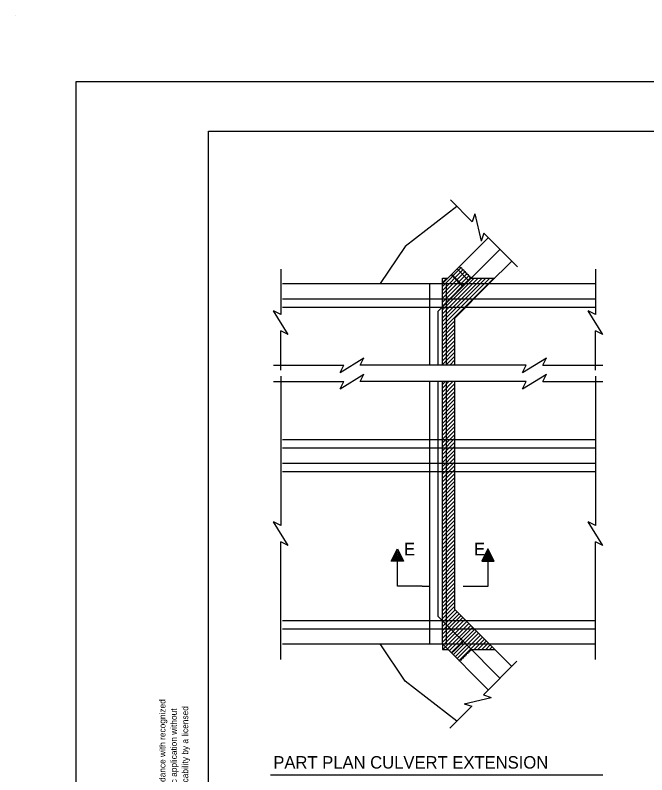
# Model space of a CAD drawing. Extents: x -0.08 to 2.83, y -0.03 to 1.92.
# Drawn here: x -0.077 to 0.718, y 0.961 to 1.917 of the extents above; entities that cross this region are included whole.
import ezdxf

# ---------------------------------------------------------------- set-up
doc = ezdxf.new("R2010")
doc.units = 0
for name, color, linetype in [('21', 7, 'Continuous'), ('50', 7, 'Continuous'), ('55', 7, 'Continuous'), ('57', 7, 'Continuous'), ('63', 7, 'Continuous')]:
    doc.layers.add(name, color=color, linetype=linetype)

msp = doc.modelspace()

# ---------------------------------------------------------------- linework, layer by layer
at = {"layer": '21'}
msp.add_line((-0.07667, 1.91667), (-0.07667, 1.91667), dxfattribs=at)
at = {"layer": '50'}
for p, q in [((0.47931, 1.67622), (0.41428, 1.62579)), ((0.46093, 1.57914), (0.51866, 1.63687)), ((0.41428, 1.62579), (0.38281, 1.57914)), ((0.49039, 1.57914), (0.5334, 1.62214)), ((0.51986, 1.57914), (0.54813, 1.60741)), ((0.49408, 1.58282), (0.47935, 1.59756)), ((0.47608, 1.58609), (0.47198, 1.59019)), ((0.48702, 1.57577), (0.47229, 1.5905)), ((0.47731, 1.58609), (0.47259, 1.5908)), ((0.48671, 1.57546), (0.47608, 1.58609)), ((0.48732, 1.57607), (0.47731, 1.58609)), ((0.25975, 1.57914), (0.46614, 1.57914)), ((0.44531, 1.47671), (0.44531, 1.57914)), ((0.46093, 1.47671), (0.46093, 1.57914)), ((0.46614, 1.47671), (0.46614, 1.57914)), ((0.46614, 1.57914), (0.65364, 1.57914)), ((0.4713, 1.56004), (0.49039, 1.57914)), ((0.47656, 1.53584), (0.51986, 1.57914)), ((0.25975, 1.56004), (0.65364, 1.56004)), ((0.45572, 1.54447), (0.4713, 1.56004)), ((0.46614, 1.56004), (0.4713, 1.56004)), ((0.25975, 1.54963), (0.65364, 1.54963)), ((0.45572, 1.47671), (0.45572, 1.54447)), ((0.47656, 1.47671), (0.47656, 1.53584)), ((0.44531, 1.12602), (0.44531, 1.45588)), ((0.45572, 1.16069), (0.45572, 1.45588)), ((0.46093, 1.12602), (0.46093, 1.45588)), ((0.46614, 1.12602), (0.46614, 1.45588)), ((0.47656, 1.16932), (0.47656, 1.45588)), ((0.25975, 1.38296), (0.65364, 1.38296)), ((0.25975, 1.37254), (0.65364, 1.37254)), ((0.25975, 1.35345), (0.65364, 1.35345)), ((0.25975, 1.34303), (0.65364, 1.34303)), ((0.47656, 1.16932), (0.51986, 1.12602)), ((0.45572, 1.16069), (0.4713, 1.14511)), ((0.25975, 1.15553), (0.65364, 1.15553)), ((0.25975, 1.14511), (0.65364, 1.14511)), ((0.46614, 1.14511), (0.4713, 1.14511)), ((0.4713, 1.14511), (0.49039, 1.12602)), ((0.48702, 1.12939), (0.47229, 1.11466)), ((0.48671, 1.1297), (0.47608, 1.11907)), ((0.48732, 1.12909), (0.47731, 1.11907)), ((0.25975, 1.12602), (0.46614, 1.12602)), ((0.41428, 1.07937), (0.38281, 1.12602)), ((0.46093, 1.12602), (0.51866, 1.06828)), ((0.46614, 1.12602), (0.65364, 1.12602)), ((0.47608, 1.11907), (0.47198, 1.11497)), ((0.47731, 1.11907), (0.47259, 1.11435)), ((0.49408, 1.12233), (0.47935, 1.1076)), ((0.49039, 1.12602), (0.5334, 1.08301)), ((0.51986, 1.12602), (0.54813, 1.09775)), ((0.47931, 1.02893), (0.41428, 1.07937))]:
    msp.add_line(p, q, dxfattribs=at)
for points in [[(0.47514, 1.58822), (0.473, 1.59036), (0.47242, 1.58979), (0.47457, 1.58764)], [(0.47729, 1.58607), (0.47514, 1.58822), (0.47457, 1.58764), (0.47671, 1.5855)], [(0.4848, 1.57856), (0.48266, 1.5807), (0.48208, 1.58013), (0.48423, 1.57798)], [(0.48695, 1.57641), (0.4848, 1.57856), (0.48423, 1.57798), (0.48637, 1.57584)], [(0.4848, 1.1266), (0.48266, 1.12446), (0.48208, 1.12503), (0.48423, 1.12718)], [(0.48695, 1.12875), (0.4848, 1.1266), (0.48423, 1.12718), (0.48637, 1.12932)], [(0.47729, 1.11909), (0.47514, 1.11694), (0.47457, 1.11751), (0.47671, 1.11966)], [(0.47514, 1.11694), (0.473, 1.11479), (0.47242, 1.11537), (0.47457, 1.11751)]]:
    msp.add_lwpolyline(points, close=True, dxfattribs=at)
at = {"layer": '55'}
for p, q in [((0.47101, 1.68452), (0.49851, 1.65703)), ((0.50177, 1.66684), (0.49851, 1.65703)), ((0.50177, 1.66684), (0.50979, 1.63267)), ((0.51306, 1.64248), (0.50979, 1.63267)), ((0.55531, 1.60023), (0.51306, 1.64248)), ((0.25781, 1.59719), (0.25781, 1.54018)), ((0.46093, 1.5755), (0.48463, 1.5992)), ((0.46093, 1.57059), (0.48703, 1.59668)), ((0.65364, 1.59719), (0.65364, 1.54018)), ((0.46093, 1.56568), (0.48965, 1.59439)), ((0.46093, 1.56077), (0.4915, 1.59133)), ((0.46093, 1.55586), (0.49417, 1.58909)), ((0.46093, 1.55095), (0.4969, 1.58692)), ((0.46093, 1.58532), (0.4617, 1.58609)), ((0.46093, 1.58041), (0.46661, 1.58609)), ((0.46093, 1.54603), (0.50098, 1.58609)), ((0.46093, 1.54112), (0.50589, 1.58609)), ((0.46093, 1.53621), (0.5108, 1.58609)), ((0.46093, 1.5313), (0.51571, 1.58609)), ((0.46093, 1.52639), (0.52062, 1.58609)), ((0.46093, 1.52148), (0.52553, 1.58609)), ((0.46093, 1.57914), (0.46093, 1.58609)), ((0.46093, 1.58609), (0.46788, 1.58609)), ((0.49734, 1.58609), (0.5268, 1.58609)), ((0.25781, 1.54018), (0.24855, 1.5448)), ((0.26705, 1.51496), (0.24855, 1.5448)), ((0.65364, 1.54018), (0.64439, 1.5448)), ((0.66289, 1.51496), (0.64439, 1.5448)), ((0.46093, 1.51657), (0.47656, 1.5322)), ((0.25781, 1.47047), (0.25781, 1.51959)), ((0.26705, 1.51496), (0.25781, 1.51959)), ((0.46093, 1.51166), (0.47656, 1.52729)), ((0.46093, 1.50675), (0.47656, 1.52238)), ((0.65364, 1.47047), (0.65364, 1.51959)), ((0.66289, 1.51496), (0.65364, 1.51959)), ((0.46093, 1.50184), (0.47656, 1.51747)), ((0.46093, 1.49693), (0.47656, 1.51256)), ((0.46093, 1.49202), (0.47656, 1.50764)), ((0.46093, 1.48711), (0.47656, 1.50273)), ((0.46093, 1.4822), (0.47656, 1.49782)), ((0.46093, 1.47729), (0.47656, 1.49291)), ((0.3321, 1.46746), (0.36193, 1.48596)), ((0.35731, 1.47671), (0.36193, 1.48596)), ((0.46526, 1.47671), (0.47656, 1.488)), ((0.47017, 1.47671), (0.47656, 1.48309)), ((0.56194, 1.46746), (0.59177, 1.48596)), ((0.58715, 1.47671), (0.59177, 1.48596)), ((0.24855, 1.47671), (0.33672, 1.47671)), ((0.3321, 1.46746), (0.33672, 1.47671)), ((0.56656, 1.47671), (0.35731, 1.47671)), ((0.47508, 1.47671), (0.47656, 1.47818)), ((0.56194, 1.46746), (0.56656, 1.47671)), ((0.58715, 1.47671), (0.66289, 1.47671)), ((0.25781, 1.46276), (0.25781, 1.27503)), ((0.3321, 1.44663), (0.36193, 1.46513)), ((0.35731, 1.45588), (0.36193, 1.46513)), ((0.56194, 1.44663), (0.59177, 1.46513)), ((0.58715, 1.45588), (0.59177, 1.46513)), ((0.65364, 1.46276), (0.65364, 1.27503)), ((0.24855, 1.45588), (0.33672, 1.45588)), ((0.3321, 1.44663), (0.33672, 1.45588)), ((0.56656, 1.45588), (0.35731, 1.45588)), ((0.46093, 1.45247), (0.46434, 1.45588)), ((0.46093, 1.44756), (0.46925, 1.45588)), ((0.46093, 1.44265), (0.47416, 1.45588)), ((0.46093, 1.43774), (0.47656, 1.45336)), ((0.56194, 1.44663), (0.56656, 1.45588)), ((0.58715, 1.45588), (0.66289, 1.45588)), ((0.46093, 1.43283), (0.47656, 1.44845)), ((0.46093, 1.42792), (0.47656, 1.44354)), ((0.46093, 1.42301), (0.47656, 1.43863)), ((0.46093, 1.4181), (0.47656, 1.43372)), ((0.46093, 1.41319), (0.47656, 1.42881)), ((0.46093, 1.40827), (0.47656, 1.4239)), ((0.46093, 1.40336), (0.47656, 1.41899)), ((0.46093, 1.39845), (0.47656, 1.41408)), ((0.46093, 1.39354), (0.47656, 1.40917)), ((0.46093, 1.38863), (0.47656, 1.40426)), ((0.46093, 1.38372), (0.47656, 1.39935)), ((0.46093, 1.37881), (0.47656, 1.39444)), ((0.46093, 1.3739), (0.47656, 1.38953)), ((0.46093, 1.36899), (0.47656, 1.38462)), ((0.46093, 1.36408), (0.47656, 1.37971)), ((0.46093, 1.35917), (0.47656, 1.3748)), ((0.46093, 1.35426), (0.47656, 1.36988)), ((0.46093, 1.34935), (0.47656, 1.36497)), ((0.46093, 1.34444), (0.47656, 1.36006)), ((0.46093, 1.33953), (0.47656, 1.35515)), ((0.46093, 1.33462), (0.47656, 1.35024)), ((0.46093, 1.32971), (0.47656, 1.34533)), ((0.46093, 1.3248), (0.47656, 1.34042)), ((0.46093, 1.31989), (0.47656, 1.33551)), ((0.46093, 1.31498), (0.47656, 1.3306)), ((0.46093, 1.31007), (0.47656, 1.32569)), ((0.46093, 1.30516), (0.47656, 1.32078)), ((0.46093, 1.30024), (0.47656, 1.31587)), ((0.46093, 1.29533), (0.47656, 1.31096)), ((0.46093, 1.29042), (0.47656, 1.30605)), ((0.46093, 1.28551), (0.47656, 1.30114)), ((0.46093, 1.2806), (0.47656, 1.29623)), ((0.46093, 1.27569), (0.47656, 1.29132)), ((0.46093, 1.27078), (0.47656, 1.28641)), ((0.46093, 1.26587), (0.47656, 1.2815)), ((0.25781, 1.27503), (0.24855, 1.27965)), ((0.26705, 1.24982), (0.24855, 1.27965)), ((0.46093, 1.26096), (0.47656, 1.27659)), ((0.46093, 1.25605), (0.47656, 1.27168)), ((0.65364, 1.27503), (0.64439, 1.27965)), ((0.66289, 1.24982), (0.64439, 1.27965)), ((0.46093, 1.25114), (0.47656, 1.26677)), ((0.46093, 1.24623), (0.47656, 1.26185)), ((0.25781, 1.10659), (0.25781, 1.25445)), ((0.26705, 1.24982), (0.25781, 1.25445)), ((0.46093, 1.24132), (0.47656, 1.25694)), ((0.46093, 1.23641), (0.47656, 1.25203)), ((0.65364, 1.10659), (0.65364, 1.25445)), ((0.66289, 1.24982), (0.65364, 1.25445)), ((0.46093, 1.2315), (0.47656, 1.24712)), ((0.46093, 1.22659), (0.47656, 1.24221)), ((0.46093, 1.22168), (0.47656, 1.2373)), ((0.46093, 1.21677), (0.47656, 1.23239)), ((0.46093, 1.21186), (0.47656, 1.22748)), ((0.46093, 1.20695), (0.47656, 1.22257)), ((0.46093, 1.20204), (0.47656, 1.21766)), ((0.46093, 1.19712), (0.47656, 1.21275)), ((0.46093, 1.19221), (0.47656, 1.20784)), ((0.43551, 1.19869), (0.44531, 1.19869)), ((0.46093, 1.1873), (0.47656, 1.20293)), ((0.46093, 1.18239), (0.47656, 1.19802)), ((0.46093, 1.17748), (0.47656, 1.19311)), ((0.46093, 1.17257), (0.47656, 1.1882)), ((0.46093, 1.16766), (0.47656, 1.18329)), ((0.46093, 1.16275), (0.47656, 1.17838)), ((0.46093, 1.15784), (0.47656, 1.17347)), ((0.46093, 1.15293), (0.47694, 1.16894)), ((0.46093, 1.14802), (0.47939, 1.16648)), ((0.46093, 1.14311), (0.48185, 1.16403)), ((0.46093, 1.1382), (0.4843, 1.16157)), ((0.46093, 1.13329), (0.48676, 1.15912)), ((0.46093, 1.12838), (0.48921, 1.15666)), ((0.46093, 1.12347), (0.49167, 1.1542)), ((0.46145, 1.11907), (0.49412, 1.15175)), ((0.46636, 1.11907), (0.49658, 1.14929)), ((0.46957, 1.11738), (0.49903, 1.14684)), ((0.47203, 1.11492), (0.50149, 1.14438)), ((0.47448, 1.11247), (0.50394, 1.14193)), ((0.47694, 1.11001), (0.5064, 1.13947)), ((0.47939, 1.10756), (0.50885, 1.13702)), ((0.48185, 1.1051), (0.51131, 1.13456)), ((0.50073, 1.11907), (0.51376, 1.13211)), ((0.50564, 1.11907), (0.51622, 1.12965)), ((0.51055, 1.11907), (0.51868, 1.1272)), ((0.46093, 1.12602), (0.46093, 1.11907)), ((0.46093, 1.11907), (0.46788, 1.11907)), ((0.49734, 1.11907), (0.5268, 1.11907)), ((0.51546, 1.11907), (0.52113, 1.12474)), ((0.52037, 1.11907), (0.52359, 1.12229)), ((0.52528, 1.11907), (0.52604, 1.11983)), ((0.55481, 1.10442), (0.51256, 1.06218)), ((0.51256, 1.06218), (0.52237, 1.0589)), ((0.48819, 1.05089), (0.52237, 1.0589)), ((0.48819, 1.05089), (0.498, 1.04762)), ((0.47051, 1.02013), (0.498, 1.04762))]:
    msp.add_line(p, q, dxfattribs=at)
for points in [[(0.43551, 1.19869), (0.40426, 1.19869), (0.40426, 1.22994), (0.39653, 1.22994), (0.40434, 1.24557), (0.41216, 1.22994), (0.40437, 1.22994), (0.40426, 1.23111), (0.39811, 1.23111), (0.40436, 1.24361), (0.41061, 1.23111), (0.40437, 1.23111), (0.40426, 1.23204), (0.39938, 1.23204), (0.40438, 1.24204), (0.40938, 1.23204), (0.40437, 1.23204), (0.40426, 1.23298), (0.4008, 1.23298), (0.40432, 1.24002), (0.40784, 1.23298), (0.40437, 1.23298), (0.40426, 1.23395), (0.40182, 1.23395), (0.40431, 1.23891), (0.40679, 1.23395), (0.40437, 1.23395), (0.40426, 1.23452), (0.40286, 1.23452), (0.4043, 1.23741), (0.40574, 1.23452), (0.40437, 1.23452), (0.40426, 1.23508), (0.40373, 1.23508), (0.40426, 1.23615), (0.40481, 1.23508), (0.40437, 1.23508)], [(0.48714, 1.19869), (0.51839, 1.19869), (0.51839, 1.22994), (0.52611, 1.22994), (0.5183, 1.24557), (0.51049, 1.22994), (0.51827, 1.22994), (0.51839, 1.23111), (0.52453, 1.23111), (0.51828, 1.24361), (0.51203, 1.23111), (0.51827, 1.23111), (0.51839, 1.23204), (0.52326, 1.23204), (0.51826, 1.24204), (0.51326, 1.23204), (0.51827, 1.23204), (0.51839, 1.23298), (0.52185, 1.23298), (0.51832, 1.24002), (0.5148, 1.23298), (0.51827, 1.23298), (0.51839, 1.23395), (0.52082, 1.23395), (0.51833, 1.23891), (0.51585, 1.23395), (0.51827, 1.23395), (0.51839, 1.23452), (0.51979, 1.23452), (0.51835, 1.23741), (0.5169, 1.23452), (0.51827, 1.23452), (0.51839, 1.23508), (0.51891, 1.23508), (0.51838, 1.23615), (0.51784, 1.23508), (0.51827, 1.23508)]]:
    msp.add_lwpolyline(points, dxfattribs=at)
for points in [[(0.48261, 1.60082), (0.48329, 1.59935), (0.48509, 1.59908), (0.48576, 1.59708), (0.48764, 1.59641), (0.4879, 1.59474), (0.48964, 1.5944), (0.48978, 1.593), (0.49118, 1.59273), (0.49165, 1.59106), (0.49332, 1.59073), (0.49352, 1.58932), (0.49506, 1.58885), (0.49513, 1.58745), (0.49666, 1.58738), (0.49734, 1.58609)], [(0.48261, 1.10434), (0.48329, 1.1058), (0.48509, 1.10607), (0.48576, 1.10808), (0.48764, 1.10875), (0.4879, 1.11042), (0.48964, 1.11075), (0.48978, 1.11216), (0.49118, 1.11243), (0.49165, 1.1141), (0.49332, 1.11443), (0.49352, 1.11584), (0.49506, 1.1163), (0.49513, 1.11771), (0.49666, 1.11778), (0.49734, 1.11907)]]:
    msp.add_spline(points, degree=3, dxfattribs=at)
at = {"layer": '57'}
msp.add_line((0.24444, 0.96151), (0.66282, 0.96151), dxfattribs=at)
at = {"layer": '63'}
for p, q in [((0, 1.83333), (2.83333, 1.83333)), ((0, 0), (0, 1.83333)), ((0.00333, 1.833), (0.00333, 1.833))]:
    msp.add_line(p, q, dxfattribs=at)
msp.add_lwpolyline([(0.16668, 0.06244), (0.16668, 1.77077), (2.72918, 1.77077), (2.72918, 0.10411), (2.56251, 0.10411), (2.56251, 0.14578), (2.07387, 0.14578), (2.07387, 0.06244)], close=True, dxfattribs=at)

# ---------------------------------------------------------------- texts
at = {"layer": '55'}
for s, height, p in [('The information presented in this Standard Detail has been prepared in accordance with recognized', 0.0078167, (0.11243, 0.59517)), ('engineering principles and is for general use. It should not be used for specific application without', 0.00781665, (0.12676, 0.59517)), ('competent professional examination and verification of its suitability and applicability by a licensed', 0.00781665, (0.14108, 0.59517))]:
    msp.add_text(s, height=height, rotation=90, dxfattribs=at).set_placement(p)
at = {"layer": '57'}
for s, height, p in [('E', 0.01562, (0.41262, 1.2376)), ('E', 0.01562, (0.50076, 1.2376)), ('PART PLAN CULVERT EXTENSION', 0.015625, (0.24816, 0.96933))]:
    msp.add_text(s, height=height, dxfattribs=at).set_placement(p)

doc.saveas('drawing.dxf')
